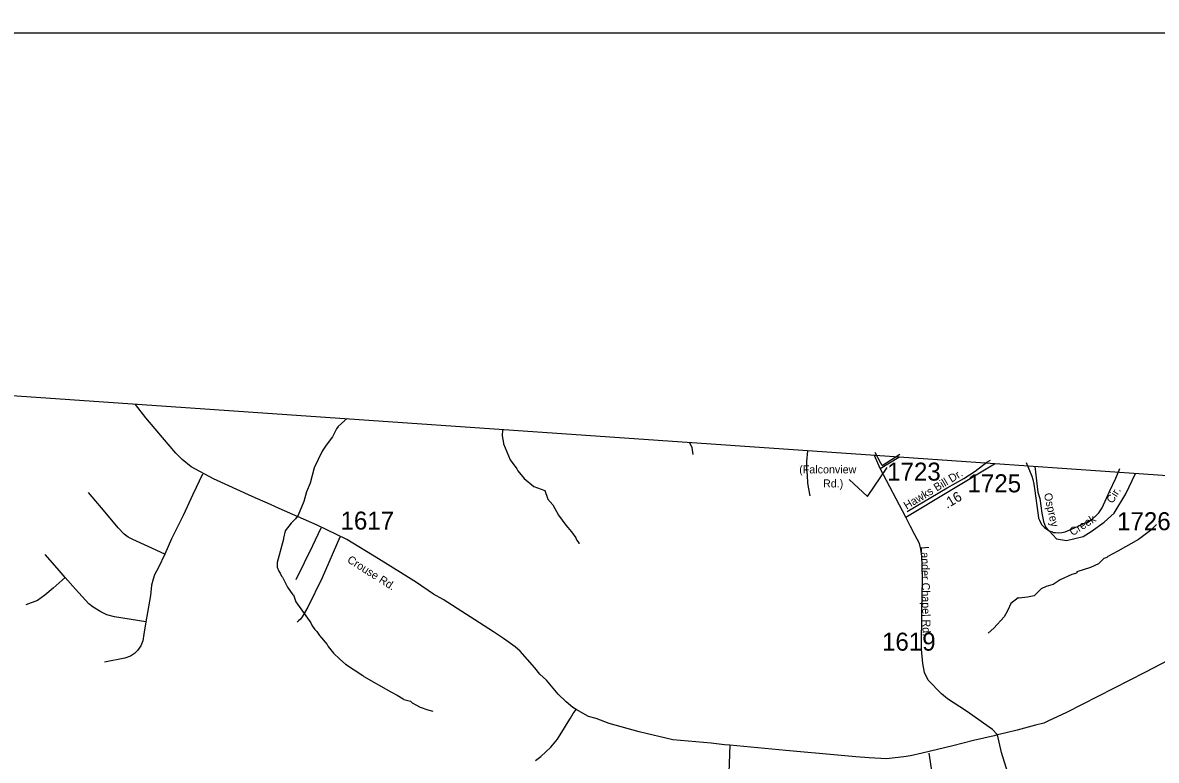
# Model space of a CAD drawing. Extents: x 1268485 to 1426702, y 514839 to 616766.
# Drawn here: x 1313854 to 1323145, y 610720 to 616766 of the extents above; entities that cross this region are included whole.
import ezdxf

# ---------------------------------------------------------------- set-up
doc = ezdxf.new("R2010")
doc.units = 0
for name, color, linetype in [('Old_Level_11', 7, 'Continuous'), ('Old_Level_17', 7, 'Continuous'), ('Old_Level_32', 7, 'Continuous'), ('Old_Level_35', 7, 'Continuous'), ('Old_Level_52', 7, 'Continuous'), ('Old_Level_62', 7, 'Continuous'), ('Old_Level_63', 7, 'Continuous'), ('Old_Level_8', 7, 'Continuous')]:
    doc.layers.add(name, color=color, linetype=linetype)

msp = doc.modelspace()

# ---------------------------------------------------------------- linework, layer by layer
at = {"layer": 'Old_Level_11'}
msp.add_line((1320217.937, 613137.218), (1320217.937, 613137.218), dxfattribs=at)
msp.add_lwpolyline([(1320627.586, 613020.881), (1320777.051, 612882.384), (1320937.589, 613120.598)], dxfattribs=at)
at = {"layer": 'Old_Level_32'}
for p, q in [((1320880.923, 613112.406), (1320833.956, 613219.405)), ((1320880.923, 613112.406), (1321035.399, 613205.298)), ((1321091.371, 612713.525), (1321817.838, 613150.484)), ((1321091.371, 612713.525), (1320880.923, 613112.406))]:
    msp.add_line(p, q, dxfattribs=at)
for points in [[(1318389.983, 611136.903), (1318361.49, 611151.88), (1318306.76, 611198.58), (1318242.371, 611262.993), (1318147.399, 611375.716), (1318092.82, 611427.543), (1318051.058, 611476.918), (1317931.697, 611615.977), (1317889.844, 611651.404), (1317793.262, 611719.683), (1317711.167, 611772.824), (1317299.08, 612037.884), (1317221.814, 612081.362), (1317081.768, 612176.372), (1316972.308, 612245.617), (1316771.095, 612372.833), (1316510.466, 612529.769), (1316267.74, 612646.598), (1315956.318, 612784.042), (1315885.332, 612817.029), (1315734.201, 612883.461), (1315416.139, 613026.863), (1315234.014, 613126.261), (1315159.444, 613185.84), (1315109.066, 613238.528), (1315044.95, 613311.832), (1314864.051, 613527.163), (1314778.605, 613637.785)], [(1322149.042, 613127.281), (1322174.238, 612917.274), (1322191.177, 612865.652), (1322206.168, 612745.701), (1322221.159, 612678.228), (1322236.149, 612633.246), (1322326.095, 612535.786), (1322408.546, 612520.792), (1322545.405, 612554.327), (1322610.925, 612595.762)], [(1322610.925, 612595.762), (1322715.861, 612670.731), (1322798.312, 612745.701), (1322895.754, 612903.137), (1322973.074, 613069.554)], [(1326334.098, 612834.096), (1325887.007, 612774.729), (1325774.804, 612760.986), (1325651.152, 612733.5), (1325575.587, 612717.467), (1325483.534, 612686.544), (1325346.601, 612637.3), (1325168.909, 612542.017), (1325042.967, 612475.592), (1324779.174, 612341.136), (1324583.221, 612236.247), (1324181.981, 612030.546), (1323497.072, 611671.12), (1323050.28, 611439.272), (1322407.858, 611111.392), (1322255.424, 611039.96), (1322221.532, 611025.298), (1322154.664, 611008.804), (1322003.524, 610968.483), (1321913.757, 610946.49), (1321842.904, 610928.792)], [(1321842.904, 610928.792), (1321801.089, 610973.982), (1321588.7, 611123.211), (1321433.545, 611223.923), (1321383.166, 611265.16), (1321275.536, 611377.416), (1321245.766, 611439.271), (1321229.736, 611512.582), (1321220.577, 611631.711), (1321222.867, 611947.861), (1321227.447, 612201.01), (1321225.157, 612320.139), (1321222.867, 612393.448), (1321213.706, 612450.722), (1321204.546, 612496.541), (1321164.292, 612569.522), (1321130.563, 612636.994), (1321091.371, 612713.525)], [(1318057.254, 610718.7), (1318099.291, 610751.573), (1318181.203, 610826.593), (1318236.683, 610893.599), (1318253.639, 610921.603), (1318287.06, 610973.775), (1318309.959, 611015.009), (1318342.018, 611065.406), (1318364.916, 611104.348), (1318389.983, 611136.903)], [(1319648.044, 610844.232), (1319604.536, 610846.523), (1319496.913, 610860.268), (1319182.055, 610889.09), (1318906.127, 610954.189), (1318661.111, 611022.911), (1318590.124, 611048.11), (1318553.486, 611061.854), (1318491.957, 611079.268), (1318389.983, 611136.903)], [(1321842.904, 610928.792), (1321815.745, 610921.748), (1321647.201, 610883.26), (1321475.91, 610838.358), (1321226.573, 610777.514), (1321128.977, 610756.572), (1321074.017, 610747.408), (1320934.327, 610731.371), (1320791.406, 610739.646), (1320682.988, 610748.31), (1320532.765, 610762.055), (1320108.659, 610800.543), (1319648.044, 610844.232)], [(1323193.278, 608381.734), (1323122.293, 608466.498), (1323042.148, 608597.082), (1322941.394, 608768.903), (1322902.467, 608814.722), (1322824.612, 608888.032), (1322504.032, 609182.418), (1322426.177, 609274.056), (1322357.481, 609351.948), (1322330.003, 609381.73), (1322307.104, 609416.094), (1322277.336, 609464.204), (1322183.378, 609696.129), (1322146.739, 609822.131), (1322045.978, 610165.772), (1322015.534, 610292.701), (1321952.229, 610513.961), (1321927.497, 610616.595), (1321876.201, 610783.375), (1321842.904, 610928.792)], [(1319648.044, 610844.232), (1319629.495, 610316.671)]]:
    msp.add_lwpolyline(points, dxfattribs=at)
at = {"layer": 'Old_Level_35'}
msp.add_line((1320897.129, 613136.129), (1321041.793, 613229.991), dxfattribs=at)
for points in [[(1320897.129, 613136.129), (1320885.646, 613156.378), (1320839.407, 613243.371)], [(1321103.514, 612760.422), (1321431.495, 612952.863), (1321568.265, 613030.732), (1321660.743, 613090.197), (1321755.785, 613163.196), (1321786.03, 613180.933)], [(1322079.049, 613161.606), (1322125.288, 613049.238), (1322132.363, 613022.889), (1322141.078, 612983.673), (1322149.485, 612927.796), (1322170.605, 612766.83), (1322175.526, 612728.946), (1322179.832, 612706.083), (1322186.497, 612688.961), (1322194.801, 612670.456), (1322207.514, 612650.617), (1322217.664, 612639.646), (1322229.147, 612628.163), (1322239.708, 612618.936), (1322254.266, 612609.299), (1322266.979, 612602.276), (1322282.768, 612595.612), (1322293.329, 612591.664), (1322302.659, 612588.64), (1322318.037, 612586.435), (1322340.901, 612584.641), (1322369.916, 612586.897), (1322398.52, 612593.869), (1322473.877, 612624.934), (1322545.03, 612657.23), (1322600.394, 612685.835), (1322620.284, 612699.061), (1322649.709, 612723.257), (1322672.983, 612749.606), (1322688.874, 612772.93), (1322699.844, 612790.565), (1322760.642, 612922.977), (1322811.598, 613032.936), (1322845.124, 613111.113)], [(1315328.325, 613065.745), (1315247.329, 612897.859), (1315169.102, 612726.948), (1315072.522, 612534.352), (1315018.081, 612408.45)], [(1315018.081, 612408.45), (1314883.156, 612471.299), (1314757.357, 612530.815), (1314717.372, 612547.937), (1314684.153, 612573.107), (1314635.043, 612626.882), (1314529.749, 612753.809), (1314392.467, 612913.955)], [(1316297.606, 612622.269), (1316230.041, 612477.04), (1316092.964, 612198.169)], [(1316453.035, 612547.937), (1316306.731, 612216.573), (1316191.901, 611976.149), (1316144.739, 611895.512), (1316129.463, 611876.289), (1316114.494, 611862.038), (1316103.114, 611852.298)], [(1314202.794, 612218.572), (1314137.485, 612296.338), (1314038.034, 612406.144)], [(1315018.081, 612408.45), (1314966.613, 612300.952), (1314934.625, 612239.129), (1314923.244, 612203.706), (1314910.633, 612155.673), (1314900.381, 612071.089), (1314877.518, 611931.499), (1314863.779, 611854.861)], [(1314202.794, 612218.572), (1314102.831, 612130.964), (1314034.138, 612072.934), (1313973.956, 612029.924), (1313879.427, 611995.475)], [(1314863.779, 611854.861), (1314606.336, 611894.949), (1314544.615, 611912.071), (1314493.25, 611937.24), (1314431.427, 611976.149), (1314394.825, 612003.575), (1314286.25, 612122.505), (1314202.794, 612218.572)], [(1314863.779, 611854.861), (1314847.785, 611754.231), (1314838.66, 611699.38), (1314821.333, 611658.164), (1314794.471, 611619.564), (1314769.865, 611595.008), (1314737.877, 611574.708), (1314689.895, 611558.663), (1314524.213, 611524.317)], [(1321279.141, 610779.26), (1321304.978, 610618.295), (1321312.872, 610562.725), (1321316.871, 610521.92), (1321319.536, 610483.37), (1321316.871, 610111.508)]]:
    msp.add_lwpolyline(points, dxfattribs=at)
at = {"layer": 'Old_Level_52'}
msp.add_lwpolyline([(1417490.345, 606272.262), (1410404.395, 606978.527), (1399228.937, 608025.409), (1372762.344, 609712.351), (1345012.522, 611503.691), (1343316.298, 611618.759), (1335764.886, 612097.479), (1329660.442, 612601.069), (1320839.383, 613219.03), (1293789.865, 615087.953), (1289276.523, 615375.373), (1273925.162, 616396.533), (1271819.299, 616532.294), (1270317.18, 616641.117), (1269751.593, 616674.893), (1268485.228, 616765.973)], dxfattribs=at)
at = {"layer": 'Old_Level_62'}
for points in [[(1316512.917, 613517.957), (1316497.634, 613509.734), (1316494.661, 613504.095), (1316439.502, 613455.446), (1316425.046, 613435.813), (1316393.57, 613370.606), (1316342, 613303.913), (1316308.884, 613254.752), (1316241.627, 613118.443), (1316210.664, 612991.26), (1316181.034, 612920.055), (1316157.145, 612840.649), (1316110.598, 612729.869), (1316089.888, 612698.394), (1316055.029, 612663.227), (1316005.612, 612600.481), (1315990.438, 612540.863), (1315991.976, 612532.866), (1315939.482, 612342.218), (1315938.56, 612302.285), (1315951.785, 612269.989), (1315963.473, 612253.738), (1315974.854, 612229.44), (1315982.646, 612221.289), (1316022.733, 612140.344), (1316067.332, 612077.599), (1316073.279, 612075.138), (1316091.939, 612018.749), (1316213.945, 611847.889), (1316225.325, 611823.642), (1316248.598, 611791.09), (1316264.182, 611774.737), (1316285.405, 611742.236), (1316349.689, 611668.725), (1316357.276, 611652.526), (1316402.08, 611599.52), (1316452.933, 611550.307), (1316499.89, 611509.194), (1316641.683, 611415.793), (1316649.578, 611407.643), (1316870.521, 611280.356), (1316921.887, 611255.135), (1316972.022, 611223.916), (1316977.046, 611217.815), (1317032.717, 611204.487), (1317046.456, 611192.133), (1317111.56, 611156.607), (1317175.024, 611133.078), (1317214.804, 611124.106)], [(1317784.782, 613430.081), (1317783.618, 613380.961), (1317795.511, 613320.676), (1317793.973, 613312.73), (1317849.03, 613183.496), (1317903.266, 613110.19), (1317910.853, 613094.042), (1317963.346, 613028.784), (1318041.881, 612964.961), (1318133.027, 612932.768), (1318156.198, 612869.766), (1318155.48, 612864.23), (1318198.336, 612815.223), (1318246.318, 612730.126), (1318304.45, 612648.771), (1318351.1, 612591.664), (1318385.959, 612542.862), (1318393.546, 612526.714), (1318410.975, 612502.313), (1318410.77, 612494.316)], [(1319319.407, 613324.049), (1319337.093, 613283.407), (1319345.808, 613227.223)], [(1320286.525, 613257.229), (1320278.282, 613168.681), (1320276.846, 613104.756), (1320283.716, 613056.62), (1320286.176, 612992.593), (1320293.046, 612944.456), (1320305.759, 612888.169)], [(1323145.525, 612651.847), (1323096.723, 612604.737), (1322999.015, 612529.175), (1322828.822, 612433.364), (1322747.827, 612391.328), (1322739.625, 612383.536), (1322715.428, 612374.156), (1322670.419, 612331.248), (1322605.726, 612300.849), (1322492.844, 612263.581), (1322492.742, 612257.583), (1322482.592, 612251.842), (1322452.347, 612242.615), (1322355.357, 612198.989), (1322298.455, 612162.388), (1322242.066, 612143.728), (1322201.67, 612124.71), (1322144.256, 612068.166), (1322087.764, 612057.811), (1322020.712, 612050.019), (1322011.895, 612051.352), (1321950.892, 612004.857), (1321927.516, 611949.493), (1321898.296, 611896.23), (1321812.071, 611802.368), (1321765.217, 611761.511)]]:
    msp.add_lwpolyline(points, dxfattribs=at)
at = {"layer": 'Old_Level_63'}
msp.add_lwpolyline([(1364464.078, 573241.255), (1364464.078, 616680.45), (1305516.95, 616680.45), (1305516.95, 588514.396)], dxfattribs=at)

# ---------------------------------------------------------------- texts
at = {"layer": 'Old_Level_11'}
for s, p in [('(Falconview ', (1320217.937, 613071.602)), ('        Rd.)', (1320217.937, 612956.773))]:
    msp.add_text(s, height=65.61666, dxfattribs=at).set_placement(p)
for s, height, rotation, p in [('Hawks Bill Dr.', 65.61666, 31.0262833, (1321098.277, 612773.692)), ('Cir.', 65.6167, 58.2454222, (1322785.93, 612820.235)), ('Osprey ', 65.6167, 282.526375, (1322222.779, 612904.002)), ('Creek', 65.6167, 32.3095806, (1322458.371, 612557.03)), ('Crouse Rd.', 65.6167, 327.6971417, (1316507.525, 612347.814)), ('Lander Chapel Rd.', 65.61666, 271.017725, (1321216.647, 612473.674))]:
    msp.add_text(s, height=height, rotation=rotation, dxfattribs=at).set_placement(p)
at = {"layer": 'Old_Level_17'}
msp.add_text('.16', height=82.0208, rotation=31.0262833, dxfattribs=at).set_placement((1321429.135, 612780.086))
at = {"layer": 'Old_Level_8'}
for s, p in [('1723', (1320938.541, 613012.571)), ('1725', (1321597.213, 612916.651)), ('1617', (1316458.476, 612611.164)), ('1726', (1322822.807, 612606.059)), ('1619', (1320896.653, 611618.77))]:
    msp.add_text(s, height=147.6375, dxfattribs=at).set_placement(p)

doc.saveas('drawing.dxf')
